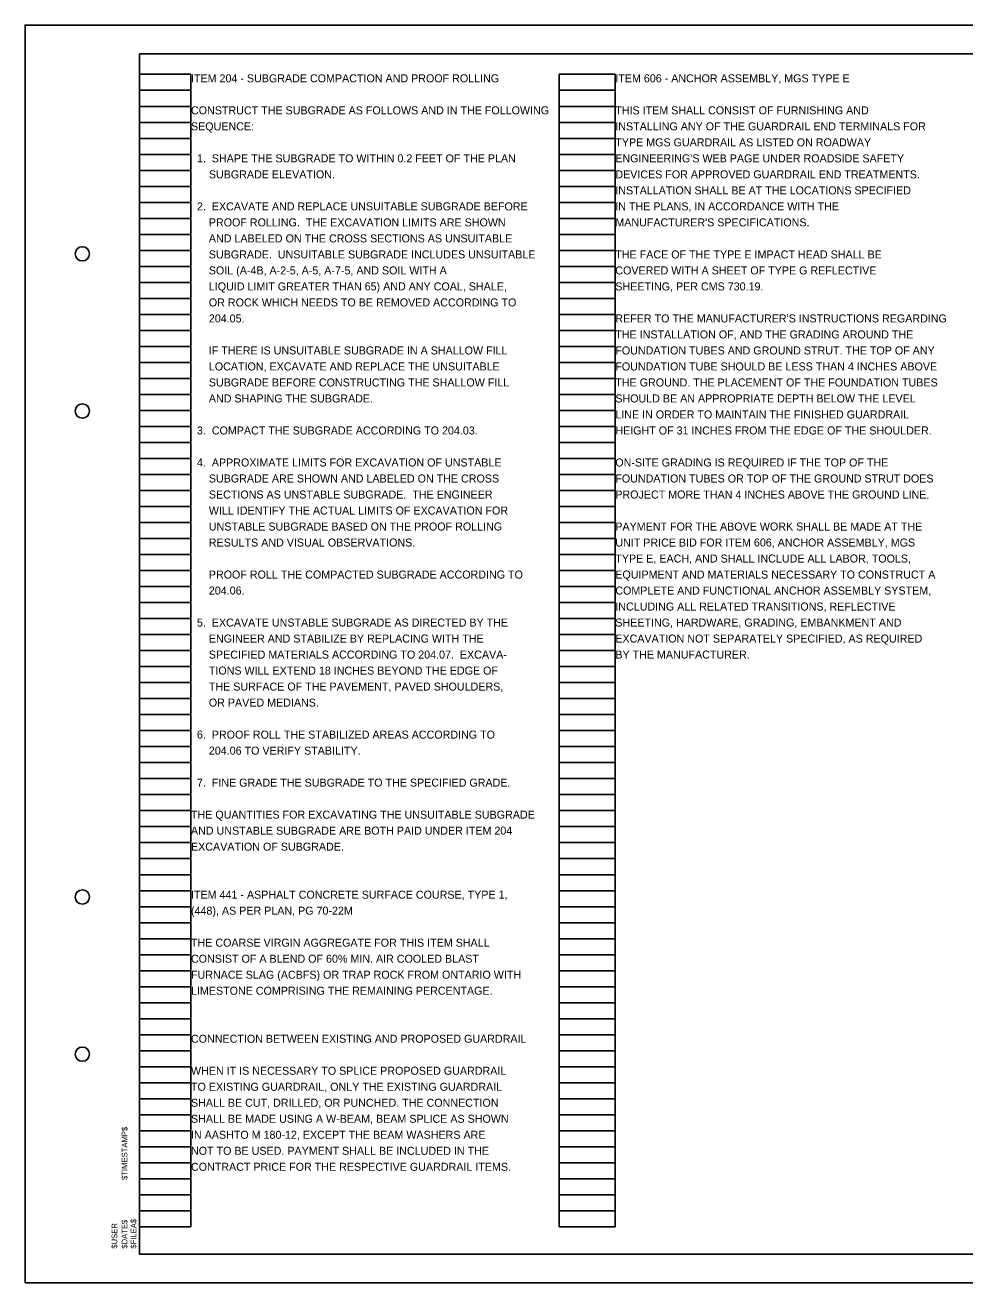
# Model space of a CAD drawing. Extents: x -13.7 to 20.3, y -10.6 to 11.4.
# Drawn here: x -13.7 to 2.73, y -10.63 to 11.37 of the extents above; entities that cross this region are included whole.
import ezdxf

# ---------------------------------------------------------------- set-up
doc = ezdxf.new("R2010")
doc.units = 0
for name, color, linetype in [('SC_Scratch1', 7, 'Continuous'), ('SH_Border', 7, 'Continuous'), ('SH_Cut_Line', 7, 'Continuous'), ('SH_Data', 7, 'Continuous'), ('SH_Text', 7, 'Continuous')]:
    doc.layers.add(name, color=color, linetype=linetype)

msp = doc.modelspace()

# ---------------------------------------------------------------- linework, layer by layer
at = {"layer": 'SC_Scratch1'}
for p, q in [((-11.699, -9.649), (-11.699, 10.511)), ((-11.699, 10.511), (-10.799, 10.511)), ((-10.799, -9.649), (-10.799, 10.511)), ((-4.359, -9.649), (-4.359, 10.511)), ((-4.359, 10.511), (-3.379, 10.511)), ((-3.379, -9.649), (-3.379, 10.511)), ((-11.699, 10.231), (-10.799, 10.231)), ((-4.359, 10.231), (-3.379, 10.231)), ((-11.699, 9.951), (-10.799, 9.951)), ((-4.359, 9.951), (-3.379, 9.951)), ((-11.699, 9.671), (-10.799, 9.671)), ((-4.359, 9.671), (-3.379, 9.671)), ((-11.699, 9.391), (-10.799, 9.391)), ((-4.359, 9.391), (-3.379, 9.391)), ((-11.699, 9.111), (-10.799, 9.111)), ((-4.359, 9.111), (-3.379, 9.111)), ((-11.699, 8.831), (-10.799, 8.831)), ((-4.359, 8.831), (-3.379, 8.831)), ((-11.699, 8.551), (-10.799, 8.551)), ((-4.359, 8.551), (-3.379, 8.551)), ((-11.699, 8.271), (-10.799, 8.271)), ((-4.359, 8.271), (-3.379, 8.271)), ((-11.699, 7.991), (-10.799, 7.991)), ((-4.359, 7.991), (-3.379, 7.991)), ((-11.699, 7.711), (-10.799, 7.711)), ((-4.359, 7.711), (-3.379, 7.711)), ((-11.699, 7.431), (-10.799, 7.431)), ((-4.359, 7.431), (-3.379, 7.431)), ((-11.699, 7.151), (-10.799, 7.151)), ((-4.359, 7.151), (-3.379, 7.151)), ((-11.699, 6.871), (-10.799, 6.871)), ((-4.359, 6.871), (-3.379, 6.871)), ((-11.699, 6.591), (-10.799, 6.591)), ((-4.359, 6.591), (-3.379, 6.591)), ((-11.699, 6.311), (-10.799, 6.311)), ((-4.359, 6.311), (-3.379, 6.311)), ((-11.699, 6.031), (-10.799, 6.031)), ((-4.359, 6.031), (-3.379, 6.031)), ((-11.699, 5.751), (-10.799, 5.751)), ((-4.359, 5.751), (-3.379, 5.751)), ((-11.699, 5.471), (-10.799, 5.471)), ((-4.359, 5.471), (-3.379, 5.471)), ((-11.699, 5.191), (-10.799, 5.191)), ((-4.359, 5.191), (-3.379, 5.191)), ((-11.699, 4.911), (-10.799, 4.911)), ((-4.359, 4.911), (-3.379, 4.911)), ((-11.699, 4.631), (-10.799, 4.631)), ((-4.359, 4.631), (-3.379, 4.631)), ((-11.699, 4.351), (-10.799, 4.351)), ((-4.359, 4.351), (-3.379, 4.351)), ((-11.699, 4.071), (-10.799, 4.071)), ((-4.359, 4.071), (-3.379, 4.071)), ((-11.699, 3.791), (-10.799, 3.791)), ((-4.359, 3.791), (-3.379, 3.791)), ((-11.699, 3.511), (-10.799, 3.511)), ((-4.359, 3.511), (-3.379, 3.511)), ((-11.699, 3.231), (-10.799, 3.231)), ((-4.359, 3.231), (-3.379, 3.231)), ((-11.699, 2.951), (-10.799, 2.951)), ((-4.359, 2.951), (-3.379, 2.951)), ((-11.699, 2.671), (-10.799, 2.671)), ((-4.359, 2.671), (-3.379, 2.671)), ((-11.699, 2.391), (-10.799, 2.391)), ((-4.359, 2.391), (-3.379, 2.391)), ((-11.699, 2.111), (-10.799, 2.111)), ((-4.359, 2.111), (-3.379, 2.111)), ((-11.699, 1.831), (-10.799, 1.831)), ((-4.359, 1.831), (-3.379, 1.831)), ((-11.699, 1.551), (-10.799, 1.551)), ((-4.359, 1.551), (-3.379, 1.551)), ((-11.699, 1.271), (-10.799, 1.271)), ((-4.359, 1.271), (-3.379, 1.271)), ((-11.699, 0.991), (-10.799, 0.991)), ((-4.359, 0.991), (-3.379, 0.991)), ((-11.699, 0.711), (-10.799, 0.711)), ((-4.359, 0.711), (-3.379, 0.711)), ((-11.699, 0.431), (-10.799, 0.431)), ((-4.359, 0.431), (-3.379, 0.431)), ((-11.699, 0.151), (-10.799, 0.151)), ((-4.359, 0.151), (-3.379, 0.151)), ((-11.699, -0.129), (-10.799, -0.129)), ((-4.359, -0.129), (-3.379, -0.129)), ((-11.699, -0.409), (-10.799, -0.409)), ((-4.359, -0.409), (-3.379, -0.409)), ((-11.699, -0.689), (-10.799, -0.689)), ((-4.359, -0.689), (-3.379, -0.689)), ((-11.699, -0.969), (-10.799, -0.969)), ((-4.359, -0.969), (-3.379, -0.969)), ((-11.699, -1.249), (-10.799, -1.249)), ((-4.359, -1.249), (-3.379, -1.249)), ((-11.699, -1.529), (-10.799, -1.529)), ((-4.359, -1.529), (-3.379, -1.529)), ((-11.699, -1.809), (-10.799, -1.809)), ((-4.359, -1.809), (-3.379, -1.809)), ((-11.699, -2.089), (-10.799, -2.089)), ((-4.359, -2.089), (-3.379, -2.089)), ((-11.699, -2.369), (-10.799, -2.369)), ((-4.359, -2.369), (-3.379, -2.369)), ((-11.699, -2.649), (-10.799, -2.649)), ((-4.359, -2.649), (-3.379, -2.649)), ((-11.699, -2.929), (-10.799, -2.929)), ((-4.359, -2.929), (-3.379, -2.929)), ((-11.699, -3.209), (-10.799, -3.209)), ((-4.359, -3.209), (-3.379, -3.209)), ((-11.699, -3.489), (-10.799, -3.489)), ((-4.359, -3.489), (-3.379, -3.489)), ((-11.699, -3.769), (-10.799, -3.769)), ((-4.359, -3.769), (-3.379, -3.769)), ((-11.699, -4.049), (-10.799, -4.049)), ((-4.359, -4.049), (-3.379, -4.049)), ((-11.699, -4.329), (-10.799, -4.329)), ((-4.359, -4.329), (-3.379, -4.329)), ((-11.699, -4.609), (-10.799, -4.609)), ((-4.359, -4.609), (-3.379, -4.609)), ((-11.699, -4.889), (-10.799, -4.889)), ((-4.359, -4.889), (-3.379, -4.889)), ((-11.699, -5.169), (-10.799, -5.169)), ((-4.359, -5.169), (-3.379, -5.169)), ((-11.699, -5.449), (-10.799, -5.449)), ((-4.359, -5.449), (-3.379, -5.449)), ((-11.699, -5.729), (-10.799, -5.729)), ((-4.359, -5.729), (-3.379, -5.729)), ((-11.699, -6.009), (-10.799, -6.009)), ((-4.359, -6.009), (-3.379, -6.009)), ((-11.699, -6.289), (-10.799, -6.289)), ((-4.359, -6.289), (-3.379, -6.289)), ((-11.699, -6.569), (-10.799, -6.569)), ((-4.359, -6.569), (-3.379, -6.569)), ((-11.699, -6.849), (-10.799, -6.849)), ((-4.359, -6.849), (-3.379, -6.849)), ((-11.699, -7.129), (-10.799, -7.129)), ((-4.359, -7.129), (-3.379, -7.129)), ((-11.699, -7.409), (-10.799, -7.409)), ((-4.359, -7.409), (-3.379, -7.409)), ((-11.699, -7.689), (-10.799, -7.689)), ((-4.359, -7.689), (-3.379, -7.689)), ((-11.699, -7.969), (-10.799, -7.969)), ((-4.359, -7.969), (-3.379, -7.969)), ((-11.699, -8.249), (-10.799, -8.249)), ((-4.359, -8.249), (-3.379, -8.249)), ((-11.699, -8.529), (-10.799, -8.529)), ((-4.359, -8.529), (-3.379, -8.529)), ((-11.699, -8.809), (-10.799, -8.809)), ((-4.359, -8.809), (-3.379, -8.809)), ((-11.699, -9.089), (-10.799, -9.089)), ((-4.359, -9.089), (-3.379, -9.089)), ((-11.699, -9.369), (-10.799, -9.369)), ((-4.359, -9.369), (-3.379, -9.369)), ((-11.699, -9.649), (-10.799, -9.649)), ((-4.359, -9.649), (-3.379, -9.649)), ((-13.699, -10.629), (-13.699, -10.629))]:
    msp.add_line(p, q, dxfattribs=at)
at = {"layer": 'SH_Border'}
msp.add_lwpolyline([(-11.699, 10.871), (19.801, 10.871), (19.801, -10.129), (-11.699, -10.129)], close=True, dxfattribs=at)
for centre in [(-12.699, 7.371), (-12.699, 4.621), (-12.699, -3.879), (-12.699, -6.629)]:
    msp.add_circle(centre, 0.125, dxfattribs=at)
at = {"layer": 'SH_Cut_Line'}
msp.add_lwpolyline([(-13.699, -10.629), (20.301, -10.629), (20.301, 11.371), (-13.699, 11.371)], close=True, dxfattribs=at)

# ---------------------------------------------------------------- texts
at = {"layer": 'SH_Data'}
for s, p in [('$TIMESTAMP$', (-11.911, -8.829)), ('$USER', (-12.088, -10.031)), ('$DATE$', (-11.911, -10.031)), ('$FILEA$', (-11.755, -10.031))]:
    msp.add_text(s, height=0.1, rotation=89.9931, dxfattribs=at).set_placement(p)
at = {"layer": 'SH_Text'}
for s, p in [('ITEM 204 - SUBGRADE COMPACTION AND PROOF ROLLING', (-10.799, 10.371)), ('ITEM 606 - ANCHOR ASSEMBLY, MGS TYPE E', (-3.379, 10.371)), ('CONSTRUCT THE SUBGRADE AS FOLLOWS AND IN THE FOLLOWING', (-10.799, 9.811)), ('THIS ITEM SHALL CONSIST OF FURNISHING AND', (-3.379, 9.811)), ('SEQUENCE:', (-10.799, 9.531)), ('INSTALLING ANY OF THE GUARDRAIL END TERMINALS FOR', (-3.379, 9.531)), ('TYPE MGS GUARDRAIL AS LISTED ON ROADWAY', (-3.379, 9.251)), ('  1.  SHAPE THE SUBGRADE TO WITHIN 0.2 FEET OF THE PLAN', (-10.799, 8.971)), ("ENGINEERING'S WEB PAGE UNDER ROADSIDE SAFETY", (-3.379, 8.971)), ('      SUBGRADE ELEVATION.', (-10.799, 8.691)), ('DEVICES FOR APPROVED GUARDRAIL END TREATMENTS.', (-3.379, 8.691)), ('INSTALLATION SHALL BE AT THE LOCATIONS SPECIFIED', (-3.379, 8.411)), ('  2.  EXCAVATE AND REPLACE UNSUITABLE SUBGRADE BEFORE', (-10.799, 8.131)), ('IN THE PLANS, IN ACCORDANCE WITH THE', (-3.379, 8.131)), ('      PROOF ROLLING.  THE EXCAVATION LIMITS ARE SHOWN', (-10.799, 7.851)), ("MANUFACTURER'S SPECIFICATIONS.", (-3.379, 7.851)), ('      AND LABELED ON THE CROSS SECTIONS AS UNSUITABLE', (-10.799, 7.571)), ('      SUBGRADE.  UNSUITABLE SUBGRADE INCLUDES UNSUITABLE', (-10.799, 7.291)), ('THE FACE OF THE TYPE E IMPACT HEAD SHALL BE', (-3.379, 7.291)), ('      SOIL (A-4B, A-2-5, A-5, A-7-5, AND SOIL WITH A', (-10.799, 7.011)), ('COVERED WITH A SHEET OF TYPE G REFLECTIVE', (-3.379, 7.011)), ('      LIQUID LIMIT GREATER THAN 65) AND ANY COAL, SHALE,', (-10.799, 6.731)), ('SHEETING, PER CMS 730.19.', (-3.379, 6.731)), ('      OR ROCK WHICH NEEDS TO BE REMOVED ACCORDING TO', (-10.799, 6.451)), ('      204.05.', (-10.799, 6.171)), ("REFER TO THE MANUFACTURER'S INSTRUCTIONS REGARDING", (-3.379, 6.171)), ('THE INSTALLATION OF, AND THE GRADING AROUND THE', (-3.379, 5.891)), ('      IF THERE IS UNSUITABLE SUBGRADE IN A SHALLOW FILL', (-10.799, 5.611)), ('FOUNDATION TUBES AND GROUND STRUT. THE TOP OF ANY', (-3.379, 5.611)), ('      LOCATION, EXCAVATE AND REPLACE THE UNSUITABLE', (-10.799, 5.331)), ('FOUNDATION TUBE SHOULD BE LESS THAN 4 INCHES ABOVE', (-3.379, 5.331)), ('      SUBGRADE BEFORE CONSTRUCTING THE SHALLOW FILL', (-10.799, 5.051)), ('THE GROUND. THE PLACEMENT OF THE FOUNDATION TUBES', (-3.379, 5.051)), ('      AND SHAPING THE SUBGRADE.', (-10.799, 4.771)), ('SHOULD BE AN APPROPRIATE DEPTH BELOW THE LEVEL', (-3.379, 4.771)), ('LINE IN ORDER TO MAINTAIN THE FINISHED GUARDRAIL', (-3.379, 4.491)), ('  3.  COMPACT THE SUBGRADE ACCORDING TO 204.03.', (-10.799, 4.211)), ('HEIGHT OF 31 INCHES FROM THE EDGE OF THE SHOULDER.', (-3.379, 4.211)), ('  4.  APPROXIMATE LIMITS FOR EXCAVATION OF UNSTABLE', (-10.799, 3.651)), ('ON-SITE GRADING IS REQUIRED IF THE TOP OF THE', (-3.379, 3.651)), ('      SUBGRADE ARE SHOWN AND LABELED ON THE CROSS', (-10.799, 3.371)), ('FOUNDATION TUBES OR TOP OF THE GROUND STRUT DOES', (-3.379, 3.371)), ('      SECTIONS AS UNSTABLE SUBGRADE.  THE ENGINEER', (-10.799, 3.091)), ('PROJECT MORE THAN 4 INCHES ABOVE THE GROUND LINE.', (-3.379, 3.091)), ('      WILL IDENTIFY THE ACTUAL LIMITS OF EXCAVATION FOR', (-10.799, 2.811)), ('      UNSTABLE SUBGRADE BASED ON THE PROOF ROLLING', (-10.799, 2.531)), ('PAYMENT FOR THE ABOVE WORK SHALL BE MADE AT THE', (-3.379, 2.531)), ('      RESULTS AND VISUAL OBSERVATIONS.', (-10.799, 2.251)), ('UNIT PRICE BID FOR ITEM 606, ANCHOR ASSEMBLY, MGS', (-3.379, 2.251)), ('TYPE E, EACH, AND SHALL INCLUDE ALL LABOR, TOOLS,', (-3.379, 1.971)), ('      PROOF ROLL THE COMPACTED SUBGRADE ACCORDING TO', (-10.799, 1.691)), ('EQUIPMENT AND MATERIALS NECESSARY TO CONSTRUCT A', (-3.379, 1.691)), ('      204.06.', (-10.799, 1.411)), ('COMPLETE AND FUNCTIONAL ANCHOR ASSEMBLY SYSTEM,', (-3.379, 1.411)), ('INCLUDING ALL RELATED TRANSITIONS, REFLECTIVE', (-3.379, 1.131)), ('  5.  EXCAVATE UNSTABLE SUBGRADE AS DIRECTED BY THE', (-10.799, 0.851)), ('SHEETING, HARDWARE, GRADING, EMBANKMENT AND', (-3.379, 0.851)), ('      ENGINEER AND STABILIZE BY REPLACING WITH THE', (-10.799, 0.571)), ('EXCAVATION NOT SEPARATELY SPECIFIED, AS REQUIRED', (-3.379, 0.571)), ('      SPECIFIED MATERIALS ACCORDING TO 204.07.  EXCAVA-', (-10.799, 0.291)), ('BY THE MANUFACTURER.', (-3.379, 0.291)), ('      TIONS WILL EXTEND 18 INCHES BEYOND THE EDGE OF', (-10.799, 0.011)), ('      THE SURFACE OF THE PAVEMENT, PAVED SHOULDERS,', (-10.799, -0.269)), ('      OR PAVED MEDIANS.', (-10.799, -0.549)), ('  6.  PROOF ROLL THE STABILIZED AREAS ACCORDING TO', (-10.799, -1.109)), ('      204.06 TO VERIFY STABILITY.', (-10.799, -1.389)), ('  7.  FINE GRADE THE SUBGRADE TO THE SPECIFIED GRADE.', (-10.799, -1.949)), ('THE QUANTITIES FOR EXCAVATING THE UNSUITABLE SUBGRADE', (-10.799, -2.509)), ('AND UNSTABLE SUBGRADE ARE BOTH PAID UNDER ITEM 204', (-10.799, -2.789)), ('EXCAVATION OF SUBGRADE.', (-10.799, -3.069)), ('ITEM 441 - ASPHALT CONCRETE SURFACE COURSE, TYPE 1, ', (-10.799, -3.909)), ('(448), AS PER PLAN, PG 70-22M', (-10.799, -4.189)), ('THE COARSE VIRGIN AGGREGATE FOR THIS ITEM SHALL ', (-10.799, -4.749)), ('CONSIST OF A BLEND OF 60% MIN. AIR COOLED BLAST ', (-10.799, -5.029)), ('FURNACE SLAG (ACBFS) OR TRAP ROCK FROM ONTARIO WITH ', (-10.799, -5.309)), ('LIMESTONE COMPRISING THE REMAINING PERCENTAGE.', (-10.799, -5.589)), ('CONNECTION BETWEEN EXISTING AND PROPOSED GUARDRAIL', (-10.799, -6.429)), ('WHEN IT IS NECESSARY TO SPLICE PROPOSED GUARDRAIL', (-10.799, -6.989)), ('TO EXISTING GUARDRAIL, ONLY THE EXISTING GUARDRAIL', (-10.799, -7.269)), ('SHALL BE CUT, DRILLED, OR PUNCHED. THE CONNECTION', (-10.799, -7.549)), ('SHALL BE MADE USING A W-BEAM, BEAM SPLICE AS SHOWN', (-10.799, -7.829)), ('IN AASHTO M 180-12, EXCEPT THE BEAM WASHERS ARE', (-10.799, -8.109)), ('NOT TO BE USED. PAYMENT SHALL BE INCLUDED IN THE', (-10.799, -8.389)), ('CONTRACT PRICE FOR THE RESPECTIVE GUARDRAIL ITEMS.', (-10.799, -8.669))]:
    msp.add_text(s, height=0.14, dxfattribs=at).set_placement(p)

doc.saveas('drawing.dxf')
